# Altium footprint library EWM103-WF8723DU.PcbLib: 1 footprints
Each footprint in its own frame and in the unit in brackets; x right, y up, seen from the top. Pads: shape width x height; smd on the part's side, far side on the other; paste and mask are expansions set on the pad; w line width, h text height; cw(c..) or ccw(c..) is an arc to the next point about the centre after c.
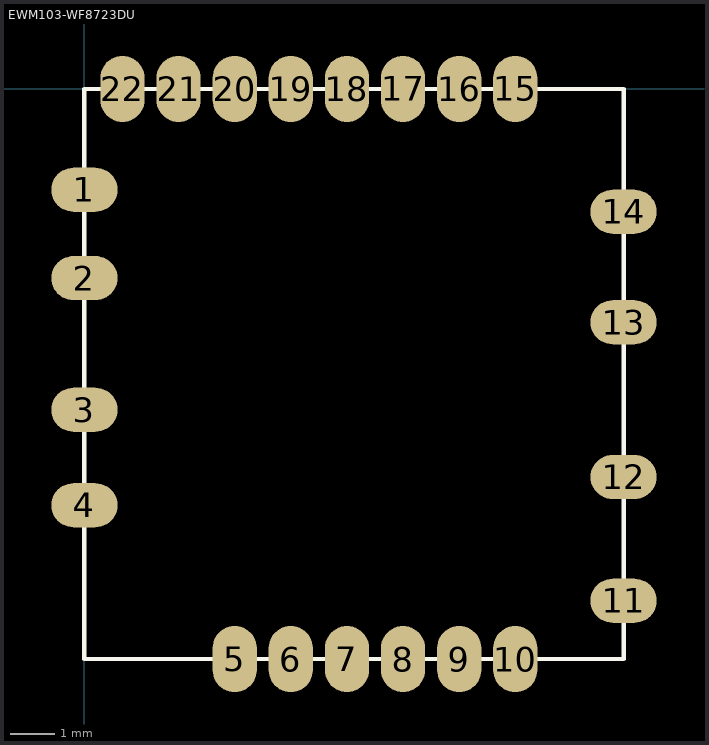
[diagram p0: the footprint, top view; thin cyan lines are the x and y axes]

## EWM103-WF8723DU [mm]
pads (22):
  oval 1.5x1 smd: 1(0,-2.28) 2(0,-4.28) 3(0,-7.26) 4(0,-9.42) 11(12.2,-11.58) 12(12.2,-8.78) 13(12.2,-5.28) 14(12.2,-2.78)
  oval 1x1.5 smd: 5(3.4,-12.9) 6(4.67,-12.9) 7(5.94,-12.9) 8(7.21,-12.9) 9(8.48,-12.9) 10(9.75,-12.9) 15(9.75,0) 16(8.48,0) 17(7.21,0) 18(5.94,0) 19(4.67,0) 20(3.4,0) 21(2.13,0) 22(0.86,0)
Top Overlay:
  lines w0.1: 0,-12.9 12.2,-12.9 12.2,0 0,0 0,-12.9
